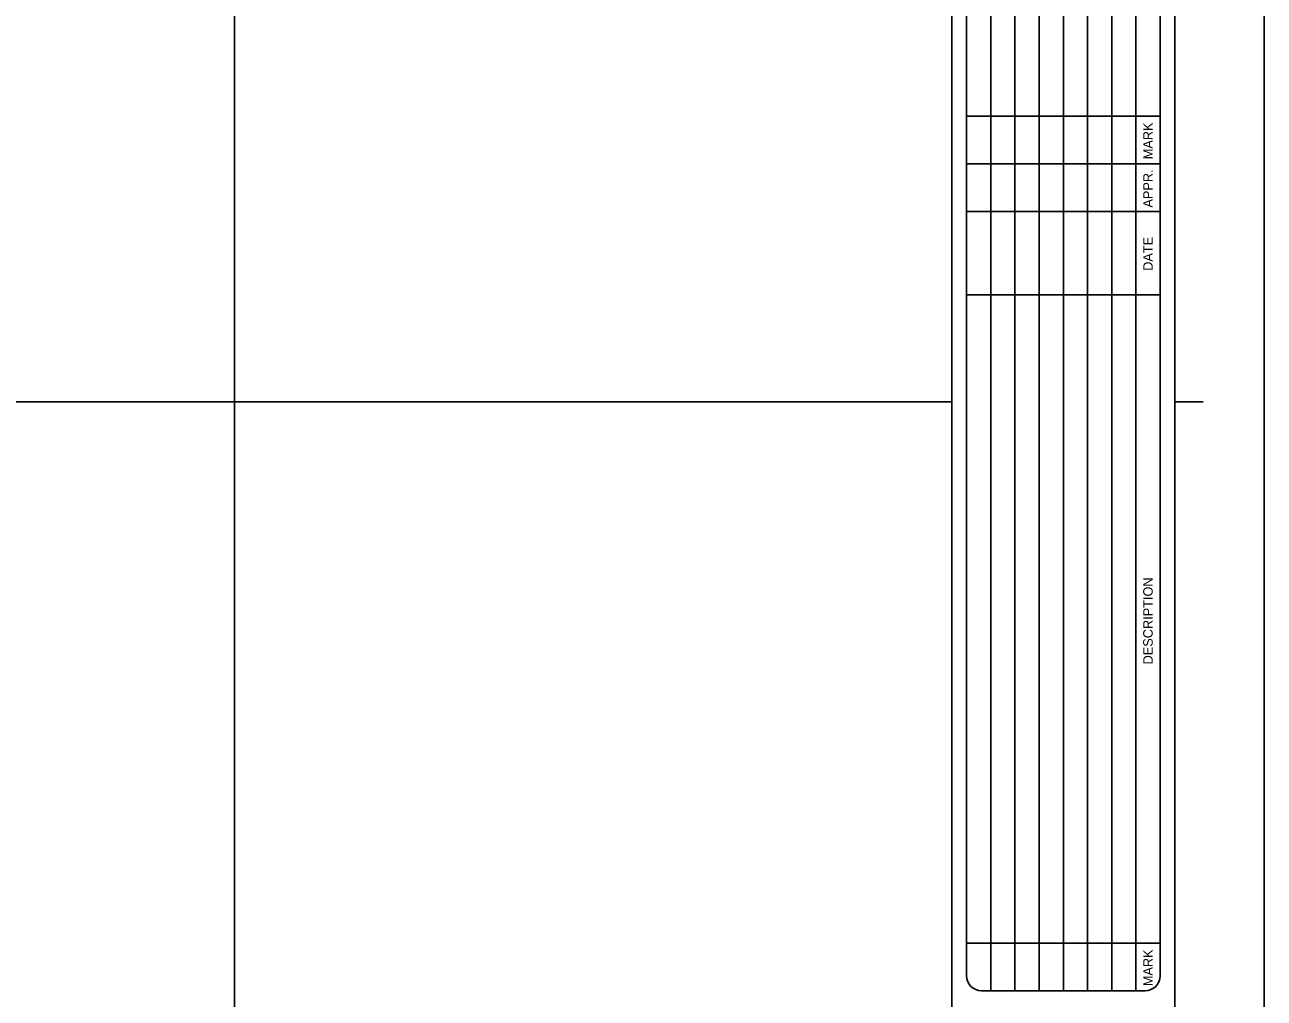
# Model space of a CAD drawing. Extents: x 0 to 3.33, y 0 to 2.33.
# Drawn here: x 2.466 to 3.333, y 0.97 to 1.652 of the extents above; entities that cross this region are included whole.
import ezdxf

# ---------------------------------------------------------------- set-up
doc = ezdxf.new("R2010")
doc.units = 0
for name, color, linetype in [('G-ANNO-NPLT', 7, 'Continuous'), ('G-ANNO-TEXT', 7, 'Continuous'), ('G-ANNO-TTLB', 7, 'Continuous'), ('G-ANNO-TTLB-GRID', 7, 'Continuous')]:
    doc.layers.add(name, color=color, linetype=linetype)

msp = doc.modelspace()

# ---------------------------------------------------------------- linework, layer by layer
at = {"layer": 'G-ANNO-NPLT'}
msp.add_lwpolyline([(0, 0), (3.33333, 0), (3.33333, 2.33333), (0, 2.33333)], close=True, dxfattribs=at)
at = {"layer": 'G-ANNO-TTLB'}
for p, q in [((3.14193, 1.5875), (3.14193, 2.04167)), ((3.15886, 1.5875), (3.15886, 2.04167)), ((3.17579, 1.5875), (3.17579, 2.04167)), ((3.19271, 1.5875), (3.19271, 2.04167)), ((3.20964, 1.5875), (3.20964, 2.04167)), ((3.22657, 1.5875), (3.22657, 2.04167)), ((3.2435, 1.5875), (3.2435, 2.04167)), ((3.12501, 1.5875), (3.14193, 1.5875)), ((3.14193, 1.55417), (3.14193, 1.5875)), ((3.14193, 1.5875), (3.15886, 1.5875)), ((3.15886, 1.55417), (3.15886, 1.5875)), ((3.15886, 1.5875), (3.17579, 1.5875)), ((3.17579, 1.55417), (3.17579, 1.5875)), ((3.17579, 1.5875), (3.19271, 1.5875)), ((3.19271, 1.55417), (3.19271, 1.5875)), ((3.19271, 1.5875), (3.20964, 1.5875)), ((3.20964, 1.55417), (3.20964, 1.5875)), ((3.20964, 1.5875), (3.22657, 1.5875)), ((3.22657, 1.5875), (3.2435, 1.5875)), ((3.22657, 1.55417), (3.22657, 1.5875)), ((3.2435, 1.55417), (3.2435, 1.5875)), ((3.2435, 1.5875), (3.26042, 1.5875)), ((3.12501, 1.55417), (3.26042, 1.55417)), ((3.14193, 1.52084), (3.14193, 1.55417)), ((3.14193, 1.52084), (3.14193, 1.55417)), ((3.15886, 1.52084), (3.15886, 1.55417)), ((3.17579, 1.52084), (3.17579, 1.55417)), ((3.19271, 1.52084), (3.19271, 1.55417)), ((3.20964, 1.52084), (3.20964, 1.55417)), ((3.22657, 1.52084), (3.22657, 1.55417)), ((3.2435, 1.52084), (3.2435, 1.55417)), ((3.12501, 1.52084), (3.14193, 1.52084)), ((3.14193, 1.52084), (3.15886, 1.52084)), ((3.14193, 1.4625), (3.14193, 1.52084)), ((3.15886, 1.4625), (3.15886, 1.52084)), ((3.15886, 1.52084), (3.17579, 1.52084)), ((3.17579, 1.4625), (3.17579, 1.52084)), ((3.17579, 1.52084), (3.19271, 1.52084)), ((3.19271, 1.4625), (3.19271, 1.52084)), ((3.19271, 1.52084), (3.20964, 1.52084)), ((3.20964, 1.4625), (3.20964, 1.52084)), ((3.20964, 1.52084), (3.22657, 1.52084)), ((3.22657, 1.4625), (3.22657, 1.52084)), ((3.22657, 1.52084), (3.2435, 1.52084)), ((3.2435, 1.52084), (3.26042, 1.52084)), ((3.2435, 1.4625), (3.2435, 1.52084)), ((3.12501, 1.4625), (3.14193, 1.4625)), ((3.14193, 1.4625), (3.15886, 1.4625)), ((3.14193, 1.00834), (3.14193, 1.4625)), ((3.15886, 1.00834), (3.15886, 1.4625)), ((3.15886, 1.4625), (3.17579, 1.4625)), ((3.17579, 1.00834), (3.17579, 1.4625)), ((3.17579, 1.4625), (3.19271, 1.4625)), ((3.19271, 1.00834), (3.19271, 1.4625)), ((3.19271, 1.4625), (3.20964, 1.4625)), ((3.20964, 1.00834), (3.20964, 1.4625)), ((3.20964, 1.4625), (3.22657, 1.4625)), ((3.22657, 1.00834), (3.22657, 1.4625)), ((3.22657, 1.4625), (3.2435, 1.4625)), ((3.2435, 1.4625), (3.26042, 1.4625)), ((3.2435, 1.00834), (3.2435, 1.4625)), ((3.29053, 1.3875), (3.27084, 1.3875)), ((3.12501, 1.00834), (3.14193, 1.00834)), ((3.14193, 0.975), (3.14193, 1.00834)), ((3.14193, 1.00834), (3.15886, 1.00834)), ((3.15886, 0.975), (3.15886, 1.00834)), ((3.15886, 1.00834), (3.17579, 1.00834)), ((3.17579, 0.975), (3.17579, 1.00834)), ((3.17579, 1.00834), (3.19271, 1.00834)), ((3.19271, 0.975), (3.19271, 1.00834)), ((3.19271, 1.00834), (3.20964, 1.00834)), ((3.20964, 0.975), (3.20964, 1.00834)), ((3.20964, 1.00834), (3.22657, 1.00834)), ((3.22657, 0.975), (3.22657, 1.00834)), ((3.22657, 1.00834), (3.2435, 1.00834)), ((3.2435, 1.00834), (3.26042, 1.00834)), ((3.2435, 0.975), (3.2435, 1.00834)), ((3.13542, 0.975), (3.25001, 0.975))]:
    msp.add_line(p, q, dxfattribs=at)
for points in [[(0.12501, 0.0625), (3.11459, 0.0625), (3.11459, 2.27084), (0.12501, 2.27084)], [(3.11459, 0.0625), (3.27084, 0.0625), (3.27084, 2.27084), (3.11459, 2.27084)]]:
    msp.add_lwpolyline(points, close=True, dxfattribs=at)
for points in [[(3.12501, 2.12292), (3.12501, 0.98542)], [(3.26042, 0.98542), (3.26042, 2.12292)]]:
    msp.add_lwpolyline(points, dxfattribs=at)
for centre, start, end in [((3.13542, 0.98542), 180, 270), ((3.25001, 0.98542), 270, 0)]:
    msp.add_arc(centre, 0.01042, start, end, dxfattribs=at)
at = {"layer": 'G-ANNO-TTLB-GRID'}
for p, q in [((2.61251, 0.0625), (2.61251, 2.27084)), ((3.11459, 1.3875), (0.12501, 1.3875))]:
    msp.add_line(p, q, dxfattribs=at)

# ---------------------------------------------------------------- texts
at = {"layer": 'G-ANNO-TEXT'}
for s, height, p in [('MARK', 0.006667, (3.25529, 1.55738)), ('APPR.', 0.006667, (3.25529, 1.52352)), ('DATE', 0.006667, (3.25529, 1.47925)), ('DESCRIPTION', 0.0066667, (3.25529, 1.20359)), ('MARK', 0.006667, (3.25529, 0.97821))]:
    msp.add_text(s, height=height, rotation=90, dxfattribs=at).set_placement(p)

doc.saveas('drawing.dxf')
